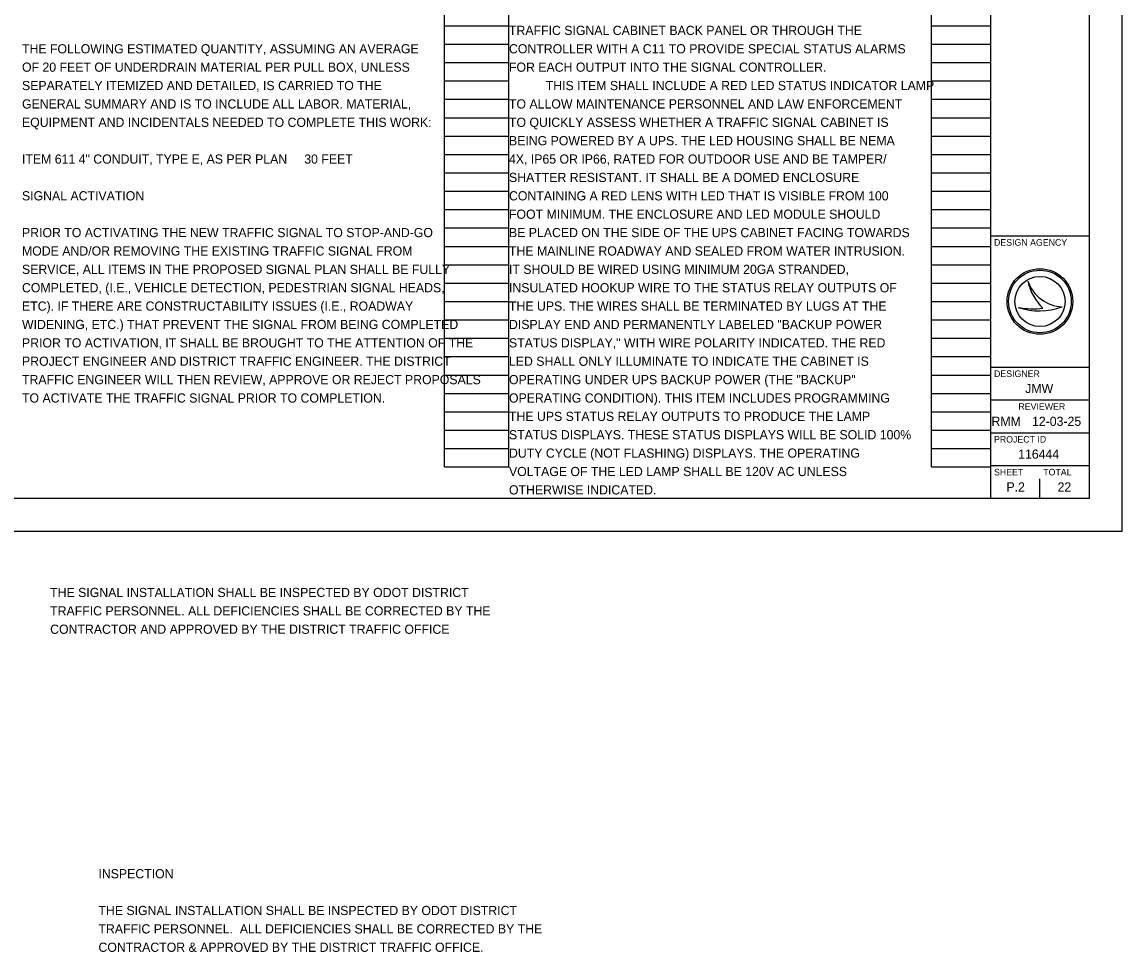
# Model space of a CAD drawing. Extents: x 0 to 54.7, y -11 to 22.
# Drawn here: x 17.24 to 34, y -6.41 to 7.76 of the extents above; entities that cross this region are included whole.
import ezdxf

# ---------------------------------------------------------------- set-up
doc = ezdxf.new("R2010")
doc.units = 0
for name, color, linetype in [('SH_Border', 7, 'Continuous'), ('SH_Cut_Line', 7, 'Continuous'), ('SH_Data', 7, 'Continuous'), ('SH_Text', 7, 'Continuous')]:
    doc.layers.add(name, color=color, linetype=linetype)

msp = doc.modelspace()

# ---------------------------------------------------------------- linework, layer by layer
at = {"layer": 'SH_Border'}
for p, q in [((32, 0.5), (32, 21.5)), ((32, 4.5), (33.5, 4.5)), ((32, 2.5), (33.5, 2.5)), ((32, 2), (33.5, 2)), ((32, 1.5), (33.5, 1.5)), ((32, 1), (33.5, 1))]:
    msp.add_line(p, q, dxfattribs=at)
msp.add_lwpolyline([(1.5, 21.5), (33.5, 21.5), (33.5, 0.5), (1.5, 0.5)], close=True, dxfattribs=at)
at = {"layer": 'SH_Cut_Line'}
msp.add_lwpolyline([(0, 0), (34, 0), (34, 22), (0, 22)], close=True, dxfattribs=at)
at = {"layer": 'SH_Data'}
for p, q in [((23.68, 0.98), (23.68, 21.14)), ((24.66, 0.98), (24.66, 21.14)), ((31.1, 0.98), (31.1, 21.14)), ((32, 0.98), (32, 21.14)), ((23.68, 7.7), (24.66, 7.7)), ((31.1, 7.7), (32, 7.7)), ((23.68, 7.42), (24.66, 7.42)), ((31.1, 7.42), (32, 7.42)), ((23.68, 7.14), (24.66, 7.14)), ((31.1, 7.14), (32, 7.14)), ((23.68, 6.86), (24.66, 6.86)), ((31.1, 6.86), (32, 6.86)), ((23.68, 6.58), (24.66, 6.58)), ((31.1, 6.58), (32, 6.58)), ((23.68, 6.3), (24.66, 6.3)), ((31.1, 6.3), (32, 6.3)), ((23.68, 6.02), (24.66, 6.02)), ((31.1, 6.02), (32, 6.02)), ((23.68, 5.74), (24.66, 5.74)), ((31.1, 5.74), (32, 5.74)), ((23.68, 5.46), (24.66, 5.46)), ((31.1, 5.46), (32, 5.46)), ((23.68, 5.18), (24.66, 5.18)), ((31.1, 5.18), (32, 5.18)), ((23.68, 4.9), (24.66, 4.9)), ((31.1, 4.9), (32, 4.9)), ((23.68, 4.62), (24.66, 4.62)), ((31.1, 4.62), (32, 4.62)), ((23.68, 4.34), (24.66, 4.34)), ((31.1, 4.34), (32, 4.34)), ((23.68, 4.06), (24.66, 4.06)), ((31.1, 4.06), (32, 4.06)), ((23.68, 3.78), (24.66, 3.78)), ((31.1, 3.78), (32, 3.78)), ((32.567, 3.81), (32.567, 3.81)), ((23.68, 3.5), (24.66, 3.5)), ((31.1, 3.5), (32, 3.5)), ((32.417, 3.41), (32.417, 3.41)), ((32.75, 3.5), (32.75, 3.5)), ((33.087, 3.419), (33.087, 3.419)), ((23.68, 3.22), (24.66, 3.22)), ((31.1, 3.22), (32, 3.22)), ((23.68, 2.94), (24.66, 2.94)), ((31.1, 2.94), (32, 2.94)), ((23.68, 2.66), (24.66, 2.66)), ((31.1, 2.66), (32, 2.66)), ((23.68, 2.38), (24.66, 2.38)), ((31.1, 2.38), (32, 2.38)), ((23.68, 2.1), (24.66, 2.1)), ((31.1, 2.1), (32, 2.1)), ((23.68, 1.82), (24.66, 1.82)), ((31.1, 1.82), (32, 1.82)), ((23.68, 1.54), (24.66, 1.54)), ((31.1, 1.54), (32, 1.54)), ((23.68, 1.26), (24.66, 1.26)), ((31.1, 1.26), (32, 1.26)), ((23.68, 0.98), (24.66, 0.98)), ((31.1, 0.98), (32, 0.98)), ((32.375, 0.675), (32.375, 0.675)), ((32.75, 0.5), (32.75, 0.8))]:
    msp.add_line(p, q, dxfattribs=at)
for radius in [0.5, 0.477, 0.477, 0.382]:
    msp.add_circle((32.75, 3.5), radius, dxfattribs=at)
for centre, radius, start, end in [((33.116, 3.998), 0.58, 198.9257, 198.9319), ((33.347, 3.97), 0.796, 191.6379, 191.6421), ((33.116, 3.998), 0.58, 198.9319, 267.1657), ((33.347, 3.97), 0.796, 191.6421, 226.0947), ((32.739, 4.37), 1.013, 251.4576, 290.0832), ((32.648, 4.654), 1.266, 259.4964, 259.4995), ((32.739, 4.37), 1.013, 251.4527, 251.4576), ((32.648, 4.654), 1.266, 259.4995, 276.6672)]:
    msp.add_arc(centre, radius, start, end, dxfattribs=at)

# ---------------------------------------------------------------- texts
for s, height, p in [('DESIGN AGENCY', 0.1, (32.05, 4.35)), ('DESIGNER', 0.1, (32.05, 2.35)), ('JMW', 0.14, (32.526, 2.105)), ('REVIEWER', 0.1, (32.422, 1.85)), ('RMM', 0.14, (32.011, 1.605)), ('12-03-25', 0.14, (32.629, 1.605)), ('PROJECT ID', 0.1, (32.05, 1.35)), ('116444', 0.14, (32.418, 1.105)), ('SHEET', 0.1, (32.05, 0.85)), ('TOTAL', 0.1, (32.8, 0.85)), ('P.2', 0.14, (32.24, 0.605)), ('22', 0.14, (33.019, 0.605))]:
    msp.add_text(s, height=height, dxfattribs=at).set_placement(p)
at = {"layer": 'SH_Text'}
for s, p in [('TRAFFIC SIGNAL CABINET BACK PANEL OR THROUGH THE', (24.66, 7.56)), ('THE FOLLOWING ESTIMATED QUANTITY, ASSUMING AN AVERAGE', (17.24, 7.28)), ('CONTROLLER WITH A C11 TO PROVIDE SPECIAL STATUS ALARMS', (24.66, 7.28)), ('OF 20 FEET OF UNDERDRAIN MATERIAL PER PULL BOX, UNLESS', (17.24, 7)), ('FOR EACH OUTPUT INTO THE SIGNAL CONTROLLER.', (24.66, 7)), ('SEPARATELY ITEMIZED AND DETAILED, IS CARRIED TO THE', (17.24, 6.72)), ('THIS ITEM SHALL INCLUDE A RED LED STATUS INDICATOR LAMP', (25.22, 6.72)), ('GENERAL SUMMARY AND IS TO INCLUDE ALL LABOR. MATERIAL,', (17.24, 6.44)), ('TO ALLOW MAINTENANCE PERSONNEL AND LAW ENFORCEMENT', (24.66, 6.44)), ('EQUIPMENT AND INCIDENTALS NEEDED TO COMPLETE THIS WORK:', (17.24, 6.16)), ('TO QUICKLY ASSESS WHETHER A TRAFFIC SIGNAL CABINET IS', (24.66, 6.16)), ('BEING POWERED BY A UPS. THE LED HOUSING SHALL BE NEMA', (24.66, 5.88)), ('ITEM 611 4" CONDUIT, TYPE E, AS PER PLAN     30 FEET', (17.24, 5.6)), ('4X, IP65 OR IP66, RATED FOR OUTDOOR USE AND BE TAMPER/', (24.66, 5.6)), ('SHATTER RESISTANT. IT SHALL BE A DOMED ENCLOSURE', (24.66, 5.32)), ('SIGNAL ACTIVATION', (17.24, 5.04)), ('CONTAINING A RED LENS WITH LED THAT IS VISIBLE FROM 100', (24.66, 5.04)), ('FOOT MINIMUM. THE ENCLOSURE AND LED MODULE SHOULD', (24.66, 4.76)), ('PRIOR TO ACTIVATING THE NEW TRAFFIC SIGNAL TO STOP-AND-GO', (17.24, 4.48)), ('BE PLACED ON THE SIDE OF THE UPS CABINET FACING TOWARDS', (24.66, 4.48)), ('MODE AND/OR REMOVING THE EXISTING TRAFFIC SIGNAL FROM', (17.24, 4.2)), ('THE MAINLINE ROADWAY AND SEALED FROM WATER INTRUSION.', (24.66, 4.2)), ('SERVICE, ALL ITEMS IN THE PROPOSED SIGNAL PLAN SHALL BE FULLY', (17.24, 3.92)), ('IT SHOULD BE WIRED USING MINIMUM 20GA STRANDED,', (24.66, 3.92)), ('COMPLETED, (I.E., VEHICLE DETECTION, PEDESTRIAN SIGNAL HEADS,', (17.24, 3.64)), ('INSULATED HOOKUP WIRE TO THE STATUS RELAY OUTPUTS OF', (24.66, 3.64)), ('ETC). IF THERE ARE CONSTRUCTABILITY ISSUES (I.E., ROADWAY', (17.24, 3.36)), ('THE UPS. THE WIRES SHALL BE TERMINATED BY LUGS AT THE', (24.66, 3.36)), ('WIDENING, ETC.) THAT PREVENT THE SIGNAL FROM BEING COMPLETED', (17.24, 3.08)), ('DISPLAY END AND PERMANENTLY LABELED "BACKUP POWER', (24.66, 3.08)), ('PRIOR TO ACTIVATION, IT SHALL BE BROUGHT TO THE ATTENTION OF THE', (17.24, 2.8)), ('STATUS DISPLAY," WITH WIRE POLARITY INDICATED. THE RED', (24.66, 2.8)), ('PROJECT ENGINEER AND DISTRICT TRAFFIC ENGINEER. THE DISTRICT', (17.24, 2.52)), ('LED SHALL ONLY ILLUMINATE TO INDICATE THE CABINET IS', (24.66, 2.52)), ('TRAFFIC ENGINEER WILL THEN REVIEW, APPROVE OR REJECT PROPOSALS', (17.24, 2.24)), ('OPERATING UNDER UPS BACKUP POWER (THE "BACKUP"', (24.66, 2.24)), ('TO ACTIVATE THE TRAFFIC SIGNAL PRIOR TO COMPLETION.', (17.24, 1.96)), ('OPERATING CONDITION). THIS ITEM INCLUDES PROGRAMMING', (24.66, 1.96)), ('THE UPS STATUS RELAY OUTPUTS TO PRODUCE THE LAMP', (24.66, 1.68)), ('STATUS DISPLAYS. THESE STATUS DISPLAYS WILL BE SOLID 100%', (24.66, 1.4)), ('DUTY CYCLE (NOT FLASHING) DISPLAYS. THE OPERATING', (24.66, 1.12)), ('VOLTAGE OF THE LED LAMP SHALL BE 120V AC UNLESS', (24.66, 0.84)), ('OTHERWISE INDICATED.', (24.66, 0.56)), ('THE SIGNAL INSTALLATION SHALL BE INSPECTED BY ODOT DISTRICT', (17.669, -1.003)), ('TRAFFIC PERSONNEL. ALL DEFICIENCIES SHALL BE CORRECTED BY THE', (17.669, -1.283)), ('CONTRACTOR AND APPROVED BY THE DISTRICT TRAFFIC OFFICE', (17.669, -1.563)), ('INSPECTION', (18.405, -5.288)), ('THE SIGNAL INSTALLATION SHALL BE INSPECTED BY ODOT DISTRICT', (18.405, -5.848)), ('TRAFFIC PERSONNEL.  ALL DEFICIENCIES SHALL BE CORRECTED BY THE', (18.405, -6.128)), ('CONTRACTOR & APPROVED BY THE DISTRICT TRAFFIC OFFICE.', (18.405, -6.408))]:
    msp.add_text(s, height=0.14, dxfattribs=at).set_placement(p)

doc.saveas('drawing.dxf')
